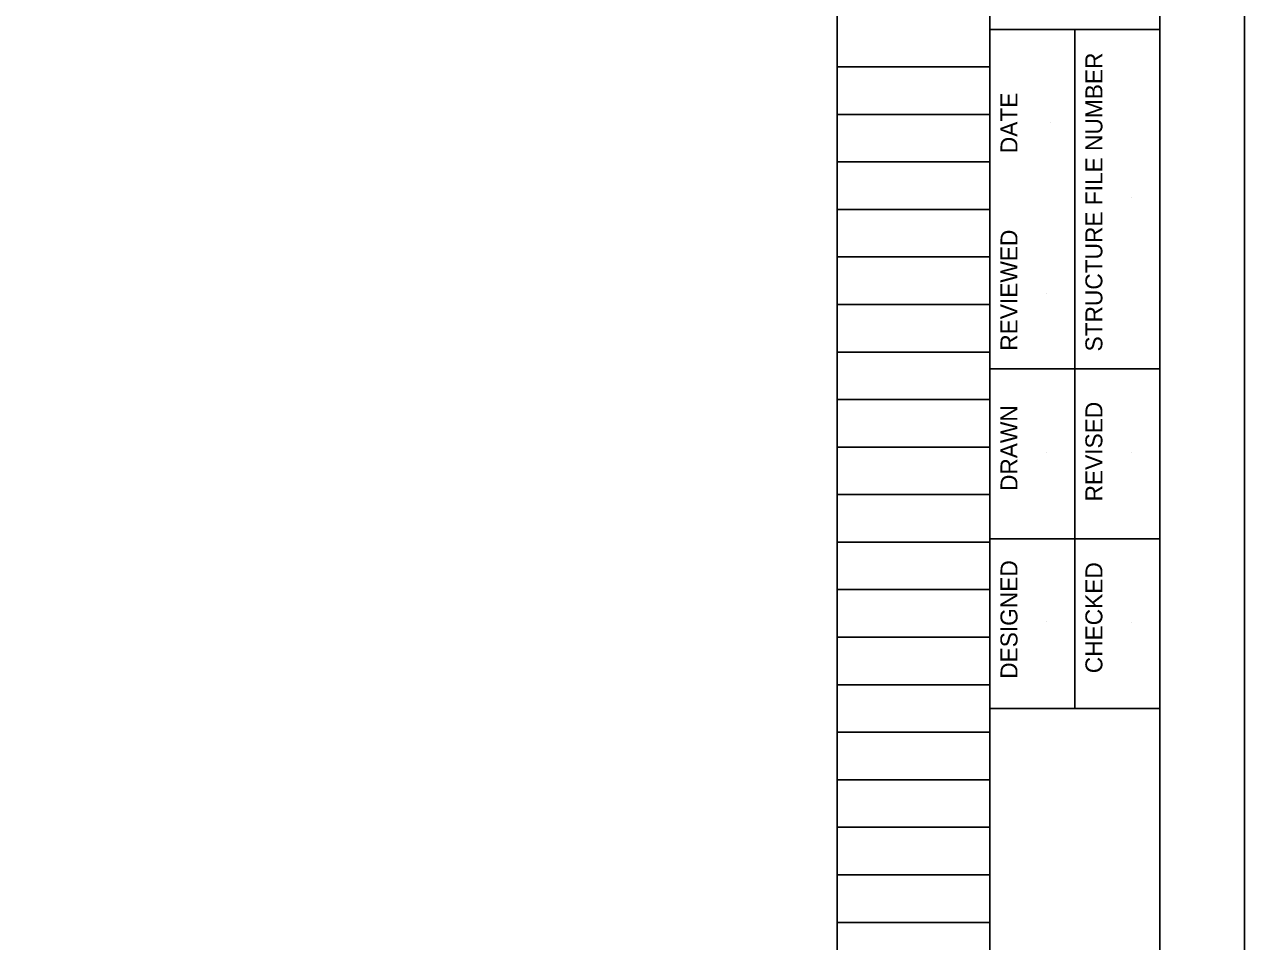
# Model space of a CAD drawing. Extents: x -0.2 to 33.8, y -0.1 to 21.9.
# Drawn here: x 26.59 to 33.78, y 12.49 to 17.9 of the extents above; entities that cross this region are included whole.
import ezdxf

# ---------------------------------------------------------------- set-up
doc = ezdxf.new("R2010")
doc.units = 0
for name, color, linetype in [('SH_Border', 7, 'Continuous'), ('SH_Cut_Line', 7, 'Continuous'), ('SH_Data', 7, 'Continuous')]:
    doc.layers.add(name, color=color, linetype=linetype)

msp = doc.modelspace()

# ---------------------------------------------------------------- linework, layer by layer
at = {"layer": 'SH_Border'}
for p, q in [((32.2753, 0.368), (32.2753, 21.368)), ((32.2753, 17.8681), (33.2753, 17.8681)), ((32.7753, 13.8681), (32.7753, 17.8681)), ((32.2753, 15.8681), (33.2753, 15.8681)), ((32.2753, 14.8681), (33.2753, 14.8681)), ((32.2753, 13.8681), (33.2753, 13.8681))]:
    msp.add_line(p, q, dxfattribs=at)
msp.add_lwpolyline([(1.7753, 21.368), (33.2753, 21.368), (33.2753, 0.368), (1.7753, 0.368)], close=True, dxfattribs=at)
at = {"layer": 'SH_Cut_Line'}
msp.add_lwpolyline([(-0.2247, 21.868), (33.7753, 21.868), (33.7753, -0.132), (-0.2247, -0.132)], close=True, dxfattribs=at)
at = {"layer": 'SH_Data'}
for p, q in [((31.3753, 0.848), (31.3753, 21.008)), ((32.2753, 0.848), (32.2753, 21.008)), ((31.3753, 17.648), (32.2753, 17.648)), ((31.3753, 17.368), (32.2753, 17.368)), ((32.6349, 17.3173), (32.6349, 17.3173)), ((31.3753, 17.088), (32.2753, 17.088)), ((33.1086, 16.877), (33.1086, 16.877)), ((31.3753, 16.808), (32.2753, 16.808)), ((31.3753, 16.528), (32.2753, 16.528)), ((32.6086, 16.3154), (32.6086, 16.3154)), ((31.3753, 16.248), (32.2753, 16.248)), ((31.3753, 15.968), (32.2753, 15.968)), ((31.3753, 15.688), (32.2753, 15.688)), ((31.3753, 15.408), (32.2753, 15.408)), ((32.6086, 15.3779), (32.6086, 15.3779)), ((33.1086, 15.3779), (33.1086, 15.3779)), ((31.3753, 15.128), (32.2753, 15.128)), ((31.3753, 14.848), (32.2753, 14.848)), ((31.3753, 14.568), (32.2753, 14.568)), ((32.6086, 14.3779), (32.6086, 14.3779)), ((33.1086, 14.377), (33.1086, 14.377)), ((31.3753, 14.288), (32.2753, 14.288)), ((31.3753, 14.008), (32.2753, 14.008)), ((31.3753, 13.728), (32.2753, 13.728)), ((31.3753, 13.448), (32.2753, 13.448)), ((31.3753, 13.168), (32.2753, 13.168)), ((31.3753, 12.888), (32.2753, 12.888)), ((31.3753, 12.608), (32.2753, 12.608))]:
    msp.add_line(p, q, dxfattribs=at)

# ---------------------------------------------------------------- texts
for s, p in [('STRUCTURE FILE NUMBER', (32.9378, 15.9713)), ('DATE', (32.4378, 17.1395)), ('REVIEWED', (32.4378, 15.9756)), ('REVISED', (32.9378, 15.0878)), ('DRAWN', (32.4378, 15.1492)), ('DESIGNED', (32.4378, 14.0429)), ('CHECKED', (32.9378, 14.0759))]:
    msp.add_text(s, height=0.1, rotation=90, dxfattribs=at).set_placement(p)

doc.saveas('drawing.dxf')
